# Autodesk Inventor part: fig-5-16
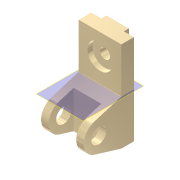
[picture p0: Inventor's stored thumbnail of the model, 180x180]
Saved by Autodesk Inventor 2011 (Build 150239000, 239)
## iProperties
Shininess: 65.0
Angle Display Precision: 2
Document Length Units: 11269
Document Angle Units: 11279
Document Time Units: 11290
Document Mass Units: 11283
Document Length Units Precision: 3
Document Angle Units Precision: 2
Compacted: False
Created: 2001-11
Part Number: fig-5-16
Document SubType Name: Modeling
Designer: Renu Muthoo
Density: 1 g/cm^3
Density: 0.0
Volumn: 0.0
Area: 0.0
PropertySet Name: Model Information
Control State: 0
Master: False
Checked Out: False
Author: Renu Muthoo
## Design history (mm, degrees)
node "Sketch1"
sketch "Sketch2"
  geometry: L1 (33.257, 104.664)-(33.257, -75.336); L2 (33.257, -75.336)-(8.257, -75.336); L3 (8.257, -75.336)-(-45.451, -59.045); L4 (-45.451, -1.628)-(8.257, 14.664); L5 (8.257, 14.664)-(8.257, 104.664); L6 (8.257, 104.664)-(33.257, 104.664); C1 r 15 at (-36.743, -30.336); A1 r 30 centre (-36.743, -30.336) between (-45.451, -1.628) and (-45.451, -59.045)
  constraints: 12 end point, 2 centre point, 2 equal length, 2 parallel, 2 point on circle, 2 tangent, 1 coincident, 1 perpendicular, 1 vertical
  dimensions: "d0" = 180 distance of L1.start L1.end; "d1" = 30 radius of A1; "d2" = 25 distance of L5.end L1.start; "d3" = 45 distance from line of L2 A1.centre; "d4" = 70 distance from line of L1 A1.centre; "d5" = 30 diameter of C1
extrude "Extrusion1" new body sketch "Sketch2" distance "d6" = 85; taper "d7" = 0 deg
workplane "Work Plane1"
sketch "Sketch3"
  geometry: L1 (15, 62.364)-(70, 62.364); L2 (70, 62.364)-(70, -52.386); L3 (70, -52.386)-(15, -52.386); L4 (15, -52.386)-(15, 62.364); L5 (0, -45)-(0, -28.708) reference
  constraints: 8 end point, 2 parallel, 1 horizontal, 1 perpendicular
  dimensions: "d8" = 55 distance of L1.start L1.end; "d9" = 15 distance between parallel lines of L5 L4
extrude "Extrusion2" cut sketch "Sketch3" distance "d10" = 50; taper "d11" = 0 deg
sketch "Sketch4"
  geometry: L1 (0, 25)-(85, 25) reference; L2 (0, 0)-(0, 25) reference; L3 (20, 25)-(65, 25); L4 (65, 25)-(65, 35); L5 (65, 35)-(20, 35); L6 (20, 35)-(20, 25)
  constraints: 8 end point, 2 parallel, 1 horizontal, 1 perpendicular, 1 point on line
  dimensions: "d12" = 45 distance of L4.end L5.end; "d13" = 10 distance of L3.end L4.end; "d14" = 20 distance between parallel lines of L2 L6
extrude "Extrusion3" join sketch "Sketch4" stored distance "d15" = 50; taper "d16" = 0 deg
sketch "Sketch5"
  geometry: L1 (85, 0)-(85, 90) reference; L2 (0, 90)-(85, 90) reference; 1 further point
  dimensions: "d17" = 42 distance from line of L2 point (42.5, 48); "d18" = 42.5 distance from line of L1 point (42.5, 48)
hole "Hole1" sketch "Sketch5" at (42.5, 48) diameter "d19" = 20; stored, may be unused: countersink angle "d23" = 82 deg, drill point angle "d25" = 118 deg; dims "d20" = 6, "d21" = 50, "d22" = 10, "d24" = 8
workplane "Work Plane7"
body "Solid1"
other parameters: "d27" = 90 deg
